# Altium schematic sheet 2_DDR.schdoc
size 302 x 215 mm
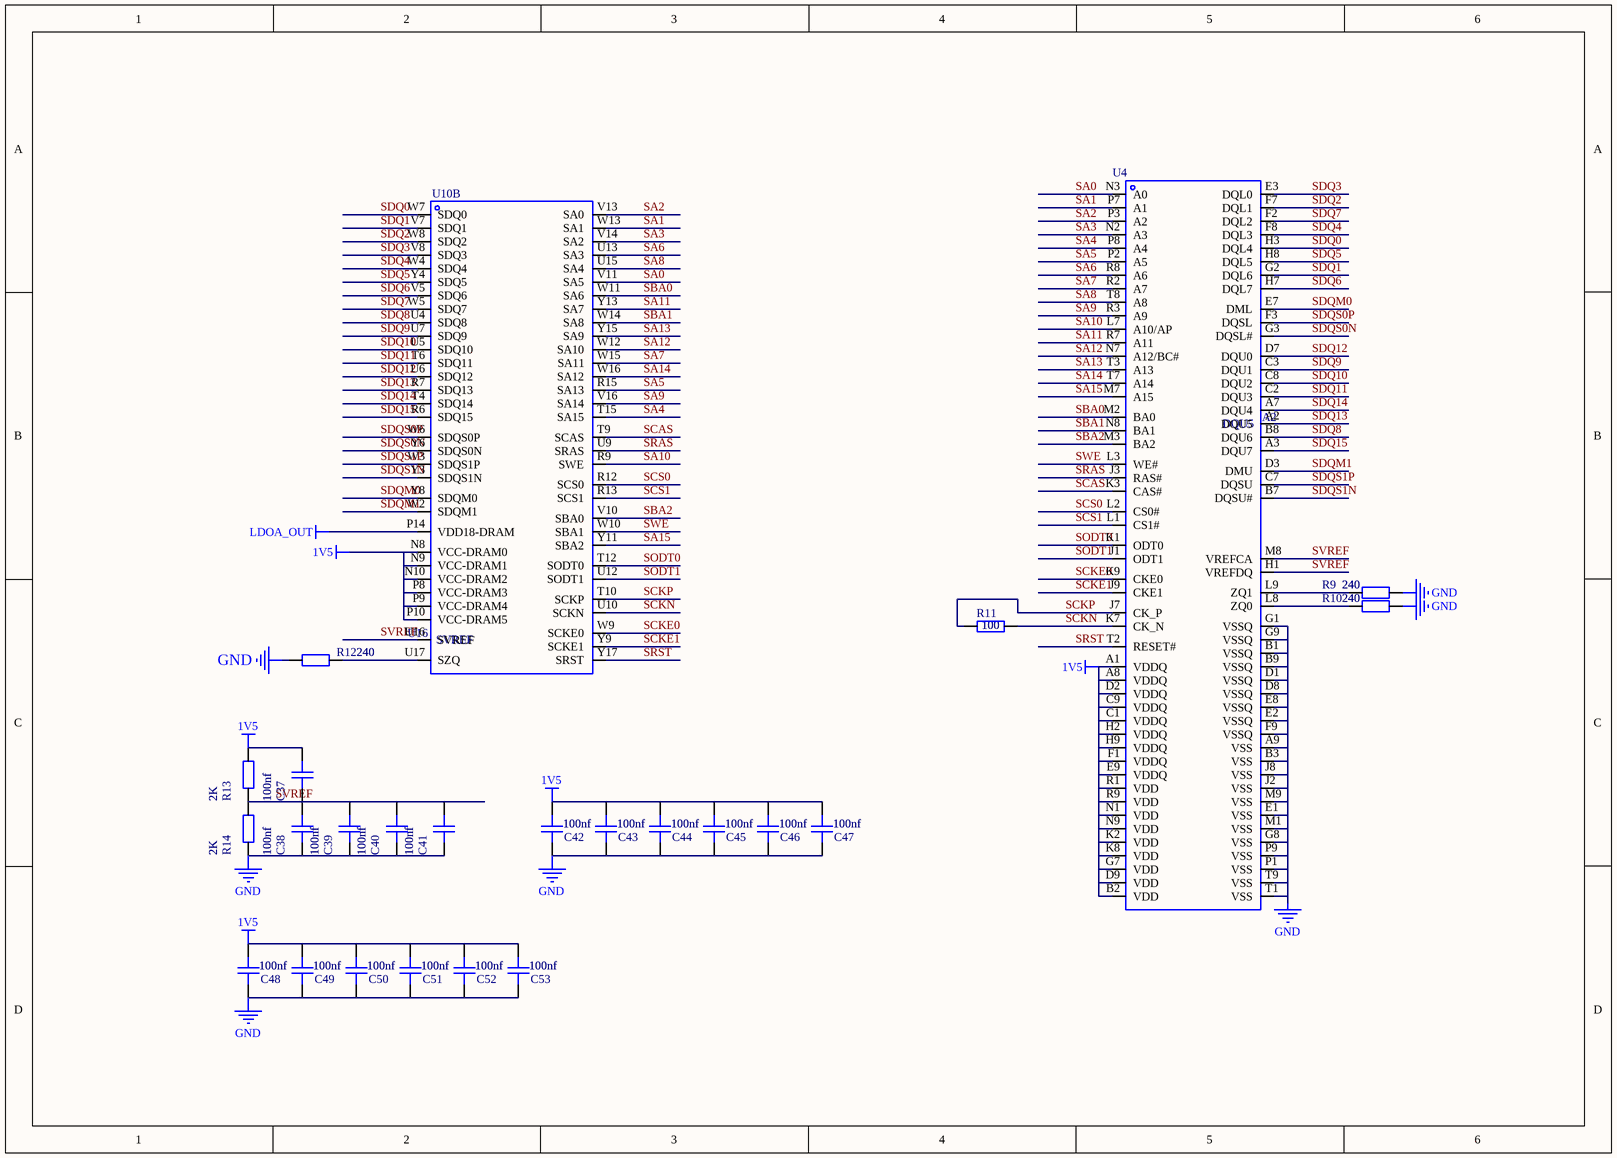
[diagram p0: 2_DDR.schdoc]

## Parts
C37  100nf
C38  100nf
C39  100nf
C40  100nf
C41  100nf
C42  100nf
C43  100nf
C44  100nf
C45  100nf
C46  100nf
C47  100nf
C48  100nf
C49  100nf
C50  100nf
C51  100nf
C52  100nf
C53  100nf
R9  240
R10  240
R11  100
R12  240
R13  2K
R14  2K
U4  NAME: DQU5  NUMBER: A2
U10  NAME: SVREF  NUMBER: U16  [ALLWINNER D1]  (part B of 10)

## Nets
1V5: C37.2 C42.2 C43.2 C44.2 C45.2 C46.2 C47.2 C48.2 C49.2 C50.2 C51.2 C52.2 C53.2 R13.2 U4.A1(VDDQ) U4.A8(VDDQ) U4.B2(VDD) U4.C1(VDDQ) U4.C9(VDDQ) U4.D2(VDDQ) U4.D9(VDD) U4.E9(VDDQ) U4.F1(VDDQ) U4.G7(VDD) U4.H2(VDDQ) U4.H9(VDDQ) U4.K2(VDD) U4.K8(VDD) U4.N1(VDD) U4.N9(VDD) U4.R1(VDD) U4.R9(VDD) U10.N8(VCC-DRAM0) U10.N9(VCC-DRAM1) U10.N10(VCC-DRAM2) U10.P8(VCC-DRAM3) U10.P9(VCC-DRAM4) U10.P10(VCC-DRAM5)
GND: C38.1 C39.1 C40.1 C41.1 C42.1 C43.1 C44.1 C45.1 C46.1 C47.1 C48.1 C49.1 C50.1 C51.1 C52.1 C53.1 R9.2 R10.2 R12.1 R14.1 U4.A9(VSS) U4.B1(VSSQ) U4.B3(VSS) U4.B9(VSSQ) U4.D1(VSSQ) U4.D8(VSSQ) U4.E1(VSS) U4.E2(VSSQ) U4.E8(VSSQ) U4.F9(VSSQ) U4.G1(VSSQ) U4.G8(VSS) U4.G9(VSSQ) U4.J2(VSS) U4.J8(VSS) U4.M1(VSS) U4.M9(VSS) U4.P1(VSS) U4.P9(VSS) U4.T1(VSS) U4.T9(VSS)
LDOA_OUT: U10.P14(VDD18-DRAM)
SA0: U4.N3(A0) U10.V11(SA5)
SA1: U4.P7(A1) U10.W13(SA1)
SA2: U4.P3(A2) U10.V13(SA0)
SA3: U4.N2(A3) U10.V14(SA2)
SA4: U4.P8(A4) U10.T15(SA15)
SA5: U4.P2(A5) U10.R15(SA13)
SA6: U4.R8(A6) U10.U13(SA3)
SA7: U4.R2(A7) U10.W15(SA11)
SA8: U4.T8(A8) U10.U15(SA4)
SA9: U4.R3(A9) U10.V16(SA14)
SA10: U4.L7(A10/AP) U10.R9(SWE)
SA11: U4.R7(A11) U10.Y13(SA7)
SA12: U4.N7(A12/BC#) U10.W12(SA10)
SA13: U4.T3(A13) U10.Y15(SA9)
SA14: U4.T7(A14) U10.W16(SA12)
SA15: U4.M7(A15) U10.Y11(SBA2)
SBA0: U4.M2(BA0) U10.W11(SA6)
SBA1: U4.N8(BA1) U10.W14(SA8)
SBA2: U4.M3(BA2) U10.V10(SBA0)
SCAS: U4.K3(CAS#) U10.T9(SCAS)
SCKE0: U4.K9(CKE0) U10.W9(SCKE0)
SCKE1: U4.J9(CKE1) U10.Y9(SCKE1)
SCKN: R11.2 U4.K7(CK_N) U10.U10(SCKN)
SCKP: R11.1 U4.J7(CK_P) U10.T10(SCKP)
SCS0: U4.L2(CS0#) U10.R12(SCS0)
SCS1: U4.L1(CS1#) U10.R13(SCS1)
SDQ0: U4.H3(DQL4) U10.W7(SDQ0)
SDQ1: U4.G2(DQL6) U10.V7(SDQ1)
SDQ2: U4.F7(DQL1) U10.W8(SDQ2)
SDQ3: U4.E3(DQL0) U10.V8(SDQ3)
SDQ4: U4.F8(DQL3) U10.W4(SDQ4)
SDQ5: U4.H8(DQL5) U10.Y4(SDQ5)
SDQ6: U4.H7(DQL7) U10.V5(SDQ6)
SDQ7: U4.F2(DQL2) U10.W5(SDQ7)
SDQ8: U4.B8(DQU6) U10.U4(SDQ8)
SDQ9: U4.C3(DQU1) U10.U7(SDQ9)
SDQ10: U4.C8(DQU2) U10.U5(SDQ10)
SDQ11: U4.C2(DQU3) U10.T6(SDQ11)
SDQ12: U4.D7(DQU0) U10.U6(SDQ12)
SDQ13: U4.A2(DQU5) U10.R7(SDQ13)
SDQ14: U4.A7(DQU4) U10.T4(SDQ14)
SDQ15: U4.A3(DQU7) U10.R6(SDQ15)
SDQM0: U4.E7(DML) U10.Y8(SDQM0)
SDQM1: U4.D3(DMU) U10.W2(SDQM1)
SDQS0N: U4.G3(DQSL#) U10.Y6(SDQS0N)
SDQS0P: U4.F3(DQSL) U10.W6(SDQS0P)
SDQS1N: U4.B7(DQSU#) U10.Y3(SDQS1N)
SDQS1P: U4.C7(DQSU) U10.W3(SDQS1P)
SODT0: U4.K1(ODT0) U10.T12(SODT0)
SODT1: U4.J1(ODT1) U10.U12(SODT1)
SRAS: U4.J3(RAS#) U10.U9(SRAS)
SRST: U4.T2(RESET#) U10.Y17(SRST)
SVREF: C37.1 C38.2 C39.2 C40.2 C41.2 R13.1 R14.2 U4.H1(VREFDQ) U4.M8(VREFCA) U10.U16(SVREF)
SWE: U4.L3(WE#) U10.W10(SBA1)
NetR9_1: R9.1 U4.L9(ZQ1)
NetR10_1: R10.1 U4.L8(ZQ0)
NetR12_2: R12.2 U10.U17(SZQ)

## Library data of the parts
C37 = C0402_1: Symbol: C0402; Convert to PCB: yes
C38-C50 C52 C53 = C0402_2: Symbol: C0402; Convert to PCB: yes
C51 = C0402_2: Symbol: C0402; Convert to PCB: yes; NUMBER: 2
R9-R12 R14 = R0402_1: Symbol: R0402; Convert to PCB: yes
R13 = R0402_1_1: Symbol: R0402; Convert to PCB: yes
U4 = H5TQ4G63EFR-RDC_1: Manufacturer: HYNIX(海力士); Pin Type: IN; Add into BOM: yes
U10 = Allwinner D1-H: Pin Type: IN; Add into BOM: yes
